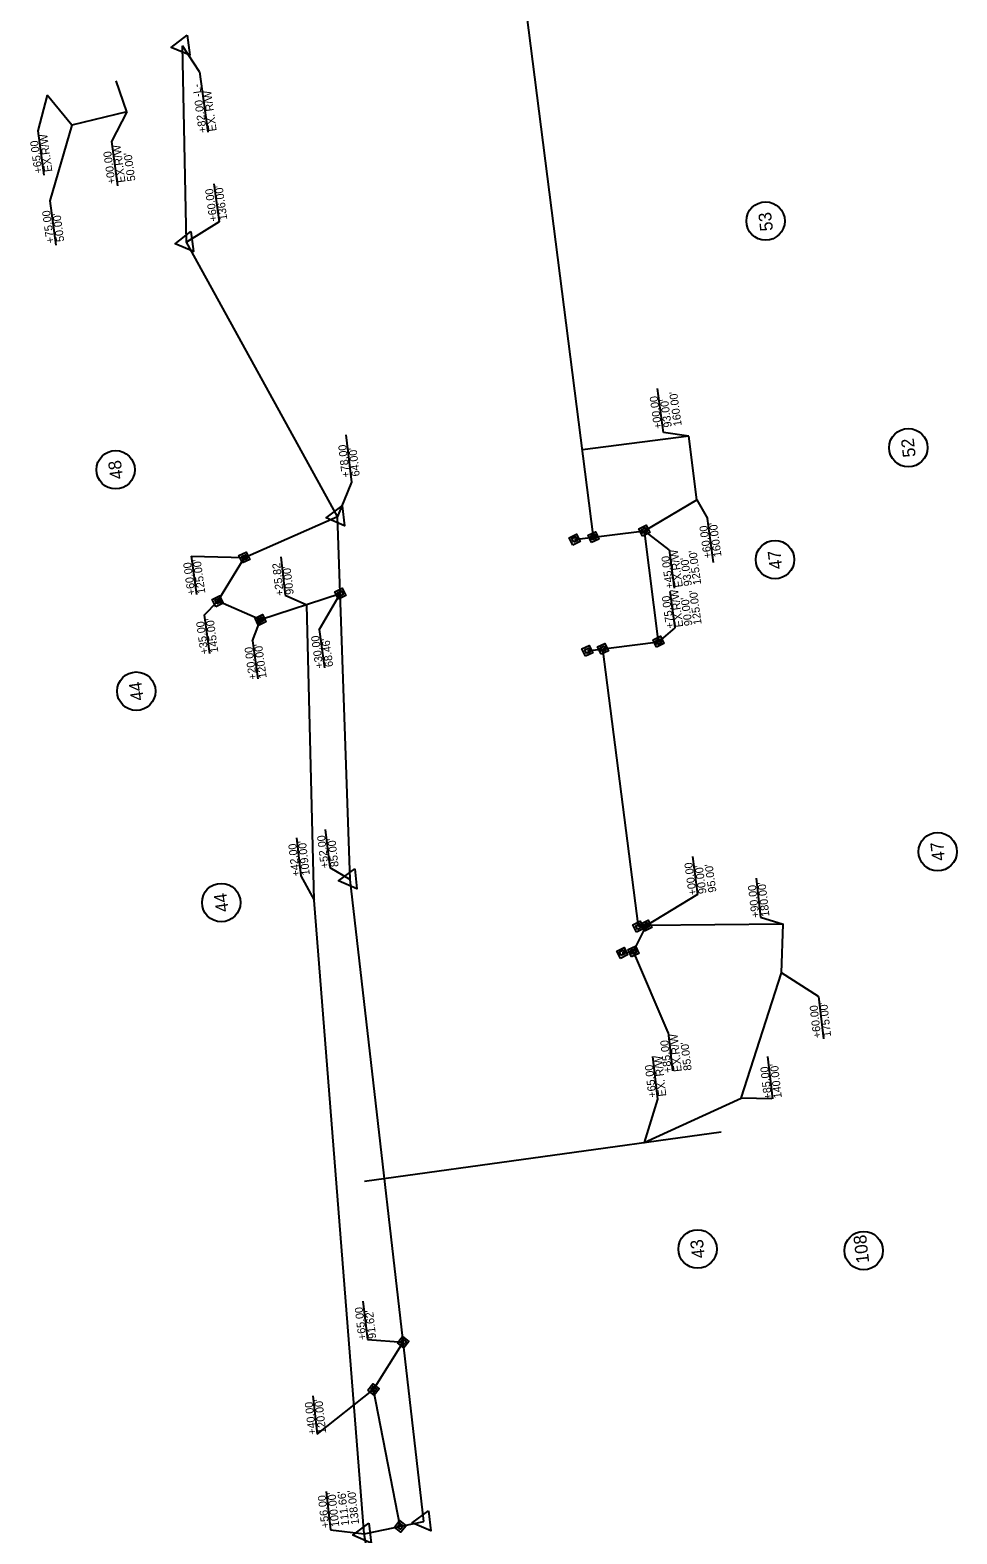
# Model space of a CAD drawing. Extents: x 474184 to 481900, y 489262 to 505659.
# Drawn here: x 477908 to 478488, y 496249 to 497189 of the extents above; entities that cross this region are included whole.
import ezdxf

# ---------------------------------------------------------------- set-up
doc = ezdxf.new("R2010")
doc.units = 0
for name, color, linetype in [('Prop Drainage Structure Outlet Berm Ditch 850 10 Label', 7, 'Continuous'), ('Prop Drainage Structure Outlet Generic CELL', 7, 'Continuous'), ('Prop Drainage Structure Pipe CSP 15in', 7, 'Continuous'), ('Prop Drainage Structure Pipe RCP 18in Class IV', 7, 'Continuous'), ('Prop Drainage Structure Pipe RCP 18in Class IV Label', 7, 'Continuous'), ('Prop Drainage Structure Pipe RCP 66in Class III', 7, 'Continuous'), ('Prop Drainage Structure Pipe Side Drain 15in Label', 7, 'Continuous'), ('Prop Drainage Structure Pipe Stub Out CELL', 7, 'Continuous'), ('Prop Drainage Structure Plot Symbol 50 Scale', 7, 'Continuous'), ('Prop Earthen Structure Base Ditch Lateral Detail Label', 7, 'Continuous'), ('Prop Earthen Structure False Sump Label', 7, 'Continuous'), ('Sheet Plot Border Inside CELL', 7, 'Continuous')]:
    doc.layers.add(name, color=color, linetype=linetype)

msp = doc.modelspace()

# ---------------------------------------------------------------- linework, layer by layer
at = {"layer": 'Prop Drainage Structure Outlet Berm Ditch 850 10 Label'}
for p, q in [((478260.5, 496872), (478204.16, 497313.42)), ((478042.36, 496859.27), (478100.59, 496884.85)), ((478025.69, 496831.94), (478042.36, 496859.27)), ((478102.24, 496836.67), (478052.38, 496820.23)), ((478052.38, 496820.23), (478025.69, 496831.94)), ((478288.55, 496628.59), (478266.39, 496802.18)), ((478285.49, 496613.08), (478293.51, 496629.22)), ((478293.51, 496629.22), (478288.55, 496628.59)), ((478278.42, 496612.17), (478285.49, 496613.08)), ((478123.03, 496339.41), (478141.57, 496368.94)), ((478139.75, 496253.81), (478123.03, 496339.41))]:
    msp.add_line(p, q, dxfattribs=at)
at = {"layer": 'Prop Drainage Structure Outlet Generic CELL'}
for p, q in [((478248.68, 496870.49), (478292.25, 496876.05)), ((478301.11, 496806.61), (478292.25, 496876.05)), ((478256.68, 496800.94), (478301.11, 496806.61))]:
    msp.add_line(p, q, dxfattribs=at)
at = {"layer": 'Prop Drainage Structure Pipe CSP 15in'}
for p, q in [((478367.98, 497069.55), (478367.98, 497069.55)), ((478457.21, 496927.89), (478457.21, 496927.89)), ((477961.85, 496914.11), (477961.85, 496914.11)), ((478373.89, 496857.97), (478373.89, 496857.97)), ((477974.77, 496775.73), (477974.77, 496775.73)), ((478475.56, 496675.42), (478475.56, 496675.42)), ((478027.85, 496643.65), (478027.85, 496643.65)), ((478325.49, 496427.13), (478325.49, 496427.13)), ((478429.28, 496426.15), (478429.28, 496426.15))]:
    msp.add_line(p, q, dxfattribs=at)
for centre in [(478367.98, 497069.55), (478457.21, 496927.89), (477961.85, 496914.11), (478373.89, 496857.97), (477974.77, 496775.73), (478475.56, 496675.42), (478027.85, 496643.65), (478325.49, 496427.13), (478429.28, 496426.15)]:
    msp.add_circle(centre, 12, dxfattribs=at)
at = {"layer": 'Prop Drainage Structure Pipe RCP 18in Class IV'}
for p, q in [((478003.75, 497178.96), (478003.75, 497178.96)), ((478006.12, 497056.27), (478006.12, 497056.27)), ((478100.59, 496884.85), (478100.59, 496884.85)), ((478292.25, 496876.05), (478292.25, 496876.05)), ((478248.68, 496870.49), (478248.68, 496870.49)), ((478260.5, 496872), (478260.5, 496872)), ((478042.36, 496859.27), (478042.36, 496859.27)), ((478102.24, 496836.67), (478102.24, 496836.67)), ((478025.69, 496831.94), (478025.69, 496831.94)), ((478052.38, 496820.23), (478052.38, 496820.23)), ((478256.68, 496800.94), (478256.68, 496800.94)), ((478266.39, 496802.18), (478266.39, 496802.18)), ((478301.11, 496806.61), (478301.11, 496806.61)), ((478108.38, 496658.01), (478108.38, 496658.01)), ((478288.55, 496628.59), (478288.55, 496628.59)), ((478293.51, 496629.22), (478293.51, 496629.22)), ((478278.42, 496612.17), (478278.42, 496612.17)), ((478285.49, 496613.08), (478285.49, 496613.08)), ((478141.57, 496368.94), (478141.57, 496368.94)), ((478123.03, 496339.41), (478123.03, 496339.41)), ((478139.75, 496253.81), (478139.75, 496253.81)), ((478154.43, 496256.89), (478154.43, 496256.89)), ((478117.24, 496249.08), (478117.24, 496249.08))]:
    msp.add_line(p, q, dxfattribs=at)
for points in [[(478006.47, 497185.64), (478008.18, 497173.28), (477996.61, 497177.95)], [(478008.84, 497062.95), (478010.55, 497050.59), (477998.98, 497055.26)], [(478103.45, 496891.47), (478104.89, 496879.08), (478093.43, 496884.01)], [(478111.24, 496664.63), (478112.67, 496652.24), (478101.21, 496657.17)], [(478157.3, 496263.51), (478158.73, 496251.11), (478147.27, 496256.04)], [(478120.11, 496255.7), (478121.54, 496243.31), (478110.08, 496248.24)]]:
    msp.add_lwpolyline(points, close=True, dxfattribs=at)
at = {"layer": 'Prop Drainage Structure Pipe RCP 18in Class IV Label'}
for points in [[(478259.33, 496868.59), (478257.1, 496873.17), (478261.68, 496875.4), (478263.91, 496870.83)], [(478291.07, 496872.65), (478288.84, 496877.22), (478293.42, 496879.45), (478295.65, 496874.88)], [(478291.66, 496874.35), (478290.54, 496876.64), (478292.83, 496877.75), (478293.95, 496875.46)], [(478247.5, 496867.08), (478245.27, 496871.66), (478249.85, 496873.89), (478252.08, 496869.32)], [(478248.09, 496868.79), (478246.97, 496871.07), (478249.26, 496872.19), (478250.38, 496869.9)], [(478259.92, 496870.3), (478258.8, 496872.58), (478261.09, 496873.7), (478262.21, 496871.41)], [(478041.19, 496855.87), (478038.96, 496860.45), (478043.53, 496862.68), (478045.76, 496858.1)], [(478041.77, 496857.57), (478040.66, 496859.86), (478042.95, 496860.97), (478044.06, 496858.69)], [(478101.07, 496833.27), (478098.84, 496837.85), (478103.42, 496840.08), (478105.65, 496835.5)], [(478101.66, 496834.97), (478100.54, 496837.26), (478102.83, 496838.38), (478103.95, 496836.09)], [(478024.51, 496828.54), (478022.28, 496833.11), (478026.86, 496835.34), (478029.09, 496830.77)], [(478025.1, 496830.24), (478023.98, 496832.53), (478026.27, 496833.64), (478027.39, 496831.36)], [(478051.21, 496816.82), (478048.98, 496821.4), (478053.56, 496823.63), (478055.79, 496819.06)], [(478051.8, 496818.53), (478050.68, 496820.81), (478052.97, 496821.93), (478054.09, 496819.64)], [(478299.94, 496803.21), (478297.71, 496807.79), (478302.28, 496810.02), (478304.51, 496805.44)], [(478300.52, 496804.91), (478299.41, 496807.2), (478301.7, 496808.31), (478302.81, 496806.03)], [(478255.51, 496797.54), (478253.28, 496802.11), (478257.86, 496804.35), (478260.09, 496799.77)], [(478256.1, 496799.24), (478254.98, 496801.53), (478257.27, 496802.64), (478258.39, 496800.36)], [(478265.22, 496798.78), (478262.99, 496803.35), (478267.56, 496805.58), (478269.8, 496801.01)], [(478265.81, 496800.48), (478264.69, 496802.77), (478266.98, 496803.88), (478268.09, 496801.6)], [(478287.38, 496625.19), (478285.15, 496629.76), (478289.72, 496631.99), (478291.96, 496627.42)], [(478287.97, 496626.89), (478286.85, 496629.18), (478289.14, 496630.29), (478290.25, 496628)], [(478292.34, 496625.82), (478290.11, 496630.4), (478294.68, 496632.63), (478296.92, 496628.05)], [(478292.93, 496627.52), (478291.81, 496629.81), (478294.1, 496630.92), (478295.21, 496628.64)], [(478277.25, 496608.77), (478275.02, 496613.35), (478279.59, 496615.58), (478281.82, 496611)], [(478277.83, 496610.47), (478276.72, 496612.76), (478279.01, 496613.88), (478280.12, 496611.59)], [(478284.32, 496609.67), (478282.09, 496614.25), (478286.66, 496616.48), (478288.9, 496611.91)], [(478284.91, 496611.38), (478283.79, 496613.66), (478286.08, 496614.78), (478287.19, 496612.49)], [(478137.99, 496368.53), (478141.15, 496372.51), (478145.14, 496369.35), (478141.98, 496365.36)], [(478139.78, 496368.73), (478141.36, 496370.73), (478143.35, 496369.14), (478141.77, 496367.15)], [(478119.46, 496338.99), (478122.62, 496342.98), (478126.61, 496339.82), (478123.45, 496335.83)], [(478121.25, 496339.2), (478122.83, 496341.19), (478124.82, 496339.61), (478123.24, 496337.62)], [(478136.18, 496253.39), (478139.34, 496257.38), (478143.33, 496254.22), (478140.16, 496250.23)], [(478137.96, 496253.6), (478139.55, 496255.59), (478141.54, 496254.01), (478139.96, 496252.02)]]:
    msp.add_lwpolyline(points, close=True, dxfattribs=at)
at = {"layer": 'Prop Drainage Structure Pipe RCP 66in Class III'}
for p, q in [((478307.67, 496864.01), (478310.98, 496840.19)), ((478308.09, 496837.93), (478311.24, 496815.3))]:
    msp.add_line(p, q, dxfattribs=at)
for points in [[(478307.67, 496864.01), (478292.25, 496876.05)], [(478311.23, 496815.36), (478301.11, 496806.61)]]:
    msp.add_lwpolyline(points, dxfattribs=at)
at = {"layer": 'Prop Drainage Structure Pipe Side Drain 15in Label'}
for p, q in [((478006.12, 497056.27), (478003.75, 497178.96)), ((478100.59, 496884.85), (478006.12, 497056.27)), ((478108.38, 496658.01), (478100.59, 496884.85)), ((478154.43, 496256.89), (478108.38, 496658.01)), ((478117.24, 496249.08), (478154.43, 496256.89)), ((478126.38, 496195.28), (478117.24, 496249.08))]:
    msp.add_line(p, q, dxfattribs=at)
at = {"layer": 'Prop Drainage Structure Pipe Stub Out CELL'}
for p, q in [((477968.94, 497137.84), (477962.19, 497157.24)), ((477934.45, 497129.54), (477919.14, 497148.12)), ((477968.94, 497137.84), (477934.45, 497129.54)), ((478320, 496935.04), (478253.54, 496926.56)), ((478325.07, 496895.36), (478320, 496935.04)), ((478292.25, 496876.05), (478325.07, 496895.36)), ((478085.84, 496645.05), (478081.41, 496829.8)), ((478117.24, 496249.08), (478085.84, 496645.05)), ((478379.09, 496630.07), (478293.51, 496629.22)), ((478377.93, 496599.68), (478379.09, 496630.07)), ((478352.67, 496521.35), (478377.93, 496599.68)), ((478292.06, 496493.73), (478352.67, 496521.35))]:
    msp.add_line(p, q, dxfattribs=at)
at = {"layer": 'Prop Drainage Structure Plot Symbol 50 Scale'}
for p, q in [((478014.23, 497162.7), (478019.46, 497125.14)), ((478023.27, 497092.87), (478026.59, 497069.05)), ((478105.81, 496935.92), (478109.21, 496906.43)), ((478092.89, 496689.38), (478095.65, 496665.49)), ((478093.41, 496275.62), (478096.16, 496251.73))]:
    msp.add_line(p, q, dxfattribs=at)
for points in [[(478014.23, 497162.7), (478003.75, 497178.96)], [(478026.59, 497069.05), (478006.12, 497056.27)], [(478109.21, 496906.43), (478100.59, 496884.85)], [(478095.65, 496665.49), (478108.38, 496658.01)], [(478096.16, 496251.73), (478117.24, 496249.08)]]:
    msp.add_lwpolyline(points, dxfattribs=at)
at = {"layer": 'Prop Earthen Structure Base Ditch Lateral Detail Label'}
for p, q in [((478009.1, 496860.03), (478012.41, 496836.21)), ((478017.19, 496823.17), (478020.51, 496799.35)), ((478089.03, 496814.24), (478092.34, 496790.42)), ((478047.41, 496807.18), (478050.73, 496783.36)), ((478322.25, 496672.46), (478325.56, 496648.64)), ((478285.49, 496613.08), (478293.51, 496629.22)), ((478278.42, 496612.17), (478285.49, 496613.08)), ((478307.17, 496562.41), (478285.49, 496613.08)), ((478307.17, 496562.41), (478309.92, 496538.52)), ((478116.41, 496394.56), (478119.17, 496370.67)), ((478085.16, 496335.35), (478087.91, 496311.46))]:
    msp.add_line(p, q, dxfattribs=at)
for points in [[(478009.1, 496860.03), (478042.36, 496859.27)], [(478089.04, 496814.14), (478102.24, 496836.67)], [(478017.19, 496823.17), (478025.69, 496831.94)], [(478047.41, 496807.18), (478052.38, 496820.23)], [(478325.56, 496648.64), (478293.51, 496629.22)], [(478119.17, 496370.67), (478141.57, 496368.94)], [(478087.91, 496311.46), (478123.03, 496339.41)]]:
    msp.add_lwpolyline(points, dxfattribs=at)
at = {"layer": 'Prop Earthen Structure False Sump Label'}
for p, q in [((477968.94, 497137.84), (477959.19, 497119.23)), ((477913.22, 497125.91), (477917.08, 497098.17)), ((477959.19, 497119.23), (477963.05, 497091.49)), ((477920.72, 497082.22), (477924.58, 497054.48)), ((478304.31, 496937.32), (478300.49, 496964.8)), ((478320, 496935.04), (478304.31, 496937.32)), ((478325.07, 496895.36), (478331.62, 496883.56)), ((478335.44, 496856.09), (478331.62, 496883.56)), ((478065.05, 496859.6), (478067.8, 496835.71)), ((478074.8, 496684.17), (478077.56, 496660.28)), ((478362.04, 496658.89), (478364.85, 496634.48)), ((478401.05, 496585.02), (478377.93, 496599.68)), ((478401.05, 496585.02), (478404.12, 496558.42)), ((478297.37, 496547.45), (478300.43, 496520.85)), ((478369.2, 496547.48), (478372.27, 496520.88)), ((478300.43, 496520.85), (478292.06, 496493.73)), ((478371.97, 496520.91), (478352.67, 496521.35))]:
    msp.add_line(p, q, dxfattribs=at)
for points in [[(477919.14, 497148.12), (477913.22, 497125.91)], [(477934.45, 497129.54), (477920.72, 497082.22)], [(478067.8, 496835.71), (478081.41, 496829.8)], [(478077.56, 496660.28), (478085.84, 496645.05)], [(478364.85, 496634.48), (478379.09, 496630.07)]]:
    msp.add_lwpolyline(points, dxfattribs=at)
at = {"layer": 'Sheet Plot Border Inside CELL'}
msp.add_line((478117.47, 496469.62), (478340.35, 496500.4), dxfattribs=at)

# ---------------------------------------------------------------- texts
at = {"layer": 'Prop Drainage Structure Pipe CSP 15in'}
for s, rotation, p in [('53', 96.57729, (478372.69, 497063.65)), ('52', 96.57729, (478461.87, 496922.34)), ('48', 97.92268, (477966.64, 496908.68)), ('47', 96.57729, (478378.57, 496852.34)), ('44', 97.92268, (477979.57, 496770.3)), ('47', 96.57729, (478480.2, 496670.14)), ('44', 97.92268, (478032.65, 496638.22)), ('43', 96.57729, (478330.14, 496421.72)), ('108', 96.57729, (478432.8, 496418.65))]:
    msp.add_text(s, height=8, rotation=rotation, dxfattribs=at).set_placement(p)
at = {"layer": 'Prop Drainage Structure Pipe RCP 66in Class III'}
for s, p in [('+45.00', (478310.59, 496840.14)), ('EX.R/W', (478316.33, 496840.94)), ("93.00'", (478322.08, 496841.74)), ("125.00'", (478327.82, 496842.54)), ('EX.R/W', (478316.59, 496816.04)), ("125.00'", (478328.08, 496817.64)), ('+75.00', (478310.85, 496815.24)), ("90.00'", (478322.34, 496816.84))]:
    msp.add_text(s, height=5, rotation=97.92268, dxfattribs=at).set_placement(p)
at = {"layer": 'Prop Drainage Structure Plot Symbol 50 Scale'}
for s, rotation, p in [('+82.00 -L-', 97.92268, (478018.84, 497125.06)), ('EX. R/W', 97.92268, (478025.03, 497125.92)), ("136.00'", 97.92268, (478031.68, 497070.5)), ('+60.00', 97.92268, (478025.49, 497069.64)), ('+78.00', 96.57729, (478108.23, 496909.53)), ("64.00'", 96.57729, (478114.44, 496910.25)), ('+52.00', 96.57729, (478095.03, 496665.42)), ("85.00'", 96.57729, (478101.23, 496666.14)), ('+56.00', 96.57729, (478095.45, 496253.05)), ("100.00'", 96.57729, (478101.66, 496253.77)), ("111.66'", 96.57729, (478107.87, 496254.49)), ("138.00'", 96.57729, (478114.08, 496255.2))]:
    msp.add_text(s, height=5, rotation=rotation, dxfattribs=at).set_placement(p)
at = {"layer": 'Prop Earthen Structure Base Ditch Lateral Detail Label'}
for s, rotation, p in [('+60.00', 97.92268, (478011.79, 496836.12)), ("125.00'", 97.92268, (478017.98, 496836.98)), ('+35.00', 97.92268, (478019.89, 496799.26)), ("145.00'", 97.92268, (478026.08, 496800.13)), ('+30.00', 97.92268, (478091.72, 496790.34)), ('+20.00', 97.92268, (478050.11, 496783.27)), ("120.00'", 97.92268, (478056.3, 496784.13)), ("68.46'", 97.92268, (478097.91, 496791.2)), ('+00.00', 97.92268, (478324.94, 496648.56)), ("90.00'", 97.92268, (478331.13, 496649.42)), ("95.00'", 97.92268, (478337.32, 496650.28)), ('+85.00', 96.57729, (478309.42, 496537.44)), ('EX.R/W', 96.57729, (478315.63, 496538.15)), ("85.00'", 96.57729, (478321.84, 496538.87)), ('+65.00', 96.57729, (478118.54, 496370.6)), ("91.62'", 96.57729, (478124.75, 496371.32)), ('+40.00', 96.57729, (478087.29, 496311.39)), ("120.00'", 96.57729, (478093.5, 496312.11))]:
    msp.add_text(s, height=5, rotation=rotation, dxfattribs=at).set_placement(p)
at = {"layer": 'Prop Earthen Structure False Sump Label'}
for s, rotation, p in [('+65.00', 97.92268, (477916.14, 497099.73)), ('EX.R/W', 97.92268, (477922.34, 497100.59)), ('+00.00', 97.92268, (477961.88, 497093.01)), ('EX.R/W', 97.92268, (477968.07, 497093.87)), ("50.00'", 97.92268, (477974.26, 497094.73)), ('+75.00', 97.92268, (477923.64, 497056.04)), ("50.00'", 97.92268, (477929.83, 497056.9)), ('+00.00', 97.92268, (478303.27, 496940.03)), ("160.00'", 97.92268, (478315.65, 496941.76)), ("93.00'", 97.92268, (478309.46, 496940.89)), ('+60.00', 97.92268, (478334.34, 496859.09)), ("160.00'", 97.92268, (478340.53, 496859.95)), ('+25.82', 96.57729, (478066.98, 496835.61)), ("90.00'", 96.57729, (478073.19, 496836.33)), ('+42.00', 96.57729, (478077.03, 496660.22)), ("109.00'", 96.57729, (478083.24, 496660.93)), ('+90.00', 96.57729, (478364.23, 496634.41)), ("180.00'", 96.57729, (478370.44, 496635.13)), ('+60.00', 96.57729, (478402.77, 496559.22)), ("175.00'", 96.57729, (478408.98, 496559.93)), ('EX. R/W', 96.57729, (478306.01, 496522.75)), ('+65.00', 96.57729, (478299.81, 496522.04)), ('+85.00', 96.57729, (478371.97, 496520.91)), ("140.00'", 96.57729, (478378.18, 496521.63))]:
    msp.add_text(s, height=5, rotation=rotation, dxfattribs=at).set_placement(p)

doc.saveas('drawing.dxf')
